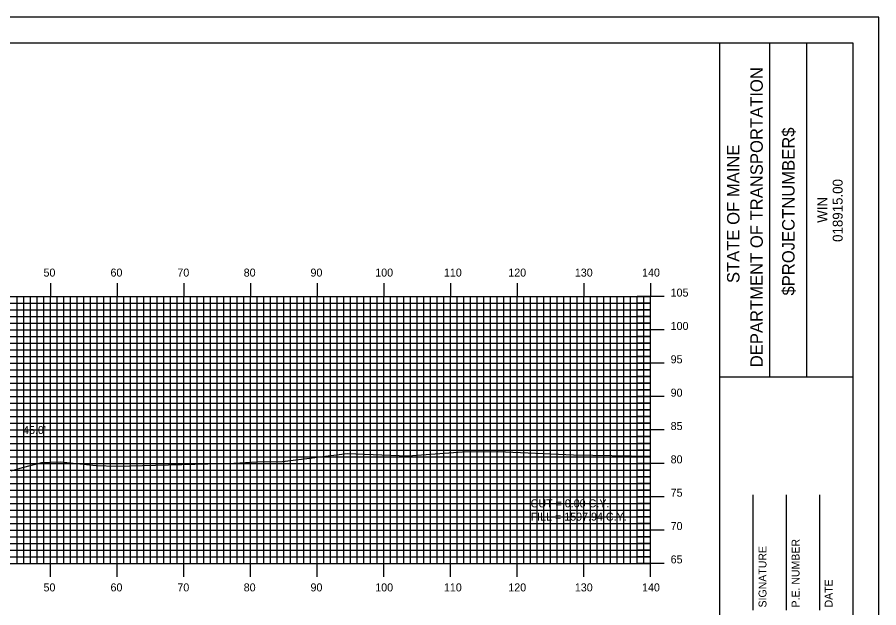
# Model space of a CAD drawing. Extents: x 857110 to 857453, y 364765 to 364985.
# Drawn here: x 857320.8 to 857450, y 364896.6 to 364985.2 of the extents above; entities that cross this region are included whole.
import ezdxf

# ---------------------------------------------------------------- set-up
doc = ezdxf.new("R2010")
doc.units = 0
for name, color, linetype in [('BORDER', 7, 'Continuous'), ('D_Text_Standard', 7, 'Continuous'), ('H_V ANNOTATION', 7, 'Continuous'), ('MAJOR', 7, 'Continuous'), ('MINOR', 7, 'Continuous'), ('PLOT BOUNDARY', 7, 'Continuous'), ('S_Roadway_Centerline', 7, 'Continuous')]:
    doc.layers.add(name, color=color, linetype=linetype)

msp = doc.modelspace()

# ---------------------------------------------------------------- linework, layer by layer
at = {"layer": 'BORDER'}
for p, q in [((857426.19, 364771.3), (857426.19, 364981.3)), ((857433.65, 364931.3), (857433.65, 364981.3)), ((857439.24, 364931.3), (857439.24, 364981.3)), ((857426.2, 364931.29), (857446.19, 364931.29)), ((857431.19, 364896.31), (857431.19, 364913.6)), ((857436.19, 364896.31), (857436.19, 364913.6)), ((857441.19, 364896.31), (857441.19, 364913.6))]:
    msp.add_line(p, q, dxfattribs=at)
msp.add_lwpolyline([(857126.19, 364771.3), (857446.19, 364771.3), (857446.19, 364981.3), (857126.19, 364981.3)], close=True, dxfattribs=at)
at = {"layer": 'MAJOR'}
for p, q in [((857325.79, 364945.31), (857325.79, 364943.3)), ((857335.79, 364945.31), (857335.79, 364943.3)), ((857345.79, 364945.31), (857345.79, 364943.3)), ((857355.79, 364945.31), (857355.79, 364943.3)), ((857365.79, 364945.31), (857365.79, 364943.3)), ((857375.79, 364945.31), (857375.79, 364943.3)), ((857385.79, 364945.31), (857385.79, 364943.3)), ((857395.79, 364945.31), (857395.79, 364943.3)), ((857405.79, 364945.31), (857405.79, 364943.3)), ((857415.79, 364945.31), (857415.79, 364943.3)), ((857135.79, 364943.3), (857415.79, 364943.3)), ((857135.79, 364943.3), (857415.79, 364943.3)), ((857325.79, 364903.3), (857325.79, 364943.3)), ((857335.79, 364903.3), (857335.79, 364943.3)), ((857345.79, 364903.3), (857345.79, 364943.3)), ((857355.79, 364903.3), (857355.79, 364943.3)), ((857365.79, 364903.3), (857365.79, 364943.3)), ((857375.79, 364903.3), (857375.79, 364943.3)), ((857385.79, 364903.3), (857385.79, 364943.3)), ((857395.79, 364903.3), (857395.79, 364943.3)), ((857405.79, 364903.3), (857405.79, 364943.3)), ((857417.8, 364943.3), (857413.79, 364943.3)), ((857415.79, 364903.3), (857415.79, 364943.3)), ((857415.79, 364903.3), (857415.79, 364943.3)), ((857135.79, 364938.3), (857415.79, 364938.3)), ((857417.8, 364938.3), (857413.79, 364938.3)), ((857135.79, 364933.3), (857415.79, 364933.3)), ((857417.8, 364933.3), (857413.79, 364933.3)), ((857135.79, 364928.3), (857415.79, 364928.3)), ((857417.8, 364928.3), (857413.79, 364928.3)), ((857135.79, 364923.3), (857415.79, 364923.3)), ((857417.8, 364923.3), (857413.79, 364923.3)), ((857135.79, 364918.3), (857415.79, 364918.3)), ((857417.8, 364918.3), (857413.79, 364918.3)), ((857135.79, 364913.3), (857415.79, 364913.3)), ((857417.8, 364913.3), (857413.79, 364913.3)), ((857135.79, 364908.3), (857415.79, 364908.3)), ((857417.8, 364908.3), (857413.79, 364908.3)), ((857135.79, 364903.3), (857415.79, 364903.3)), ((857135.79, 364903.3), (857415.79, 364903.3)), ((857325.79, 364901.3), (857325.79, 364903.3)), ((857335.79, 364901.3), (857335.79, 364903.3)), ((857345.79, 364901.3), (857345.79, 364903.3)), ((857355.79, 364901.3), (857355.79, 364903.3)), ((857365.79, 364901.3), (857365.79, 364903.3)), ((857375.79, 364901.3), (857375.79, 364903.3)), ((857385.79, 364901.3), (857385.79, 364903.3)), ((857395.79, 364901.3), (857395.79, 364903.3)), ((857405.79, 364901.3), (857405.79, 364903.3)), ((857417.8, 364903.3), (857413.79, 364903.3)), ((857415.79, 364901.3), (857415.79, 364903.3))]:
    msp.add_line(p, q, dxfattribs=at)
at = {"layer": 'MINOR'}
for p, q in [((857320.79, 364903.3), (857320.79, 364943.3)), ((857321.79, 364903.3), (857321.79, 364943.3)), ((857322.79, 364903.3), (857322.79, 364943.3)), ((857323.79, 364903.3), (857323.79, 364943.3)), ((857324.79, 364903.3), (857324.79, 364943.3)), ((857326.79, 364903.3), (857326.79, 364943.3)), ((857327.79, 364903.3), (857327.79, 364943.3)), ((857328.79, 364903.3), (857328.79, 364943.3)), ((857329.79, 364903.3), (857329.79, 364943.3)), ((857330.79, 364903.3), (857330.79, 364943.3)), ((857331.79, 364903.3), (857331.79, 364943.3)), ((857332.79, 364903.3), (857332.79, 364943.3)), ((857333.79, 364903.3), (857333.79, 364943.3)), ((857334.79, 364903.3), (857334.79, 364943.3)), ((857336.79, 364903.3), (857336.79, 364943.3)), ((857337.79, 364903.3), (857337.79, 364943.3)), ((857338.79, 364903.3), (857338.79, 364943.3)), ((857339.79, 364903.3), (857339.79, 364943.3)), ((857340.79, 364903.3), (857340.79, 364943.3)), ((857341.79, 364903.3), (857341.79, 364943.3)), ((857342.79, 364903.3), (857342.79, 364943.3)), ((857343.79, 364903.3), (857343.79, 364943.3)), ((857344.79, 364903.3), (857344.79, 364943.3)), ((857346.79, 364903.3), (857346.79, 364943.3)), ((857347.79, 364903.3), (857347.79, 364943.3)), ((857348.79, 364903.3), (857348.79, 364943.3)), ((857349.79, 364903.3), (857349.79, 364943.3)), ((857350.79, 364903.3), (857350.79, 364943.3)), ((857351.79, 364903.3), (857351.79, 364943.3)), ((857352.79, 364903.3), (857352.79, 364943.3)), ((857353.79, 364903.3), (857353.79, 364943.3)), ((857354.79, 364903.3), (857354.79, 364943.3)), ((857356.79, 364903.3), (857356.79, 364943.3)), ((857357.79, 364903.3), (857357.79, 364943.3)), ((857358.79, 364903.3), (857358.79, 364943.3)), ((857359.79, 364903.3), (857359.79, 364943.3)), ((857360.79, 364903.3), (857360.79, 364943.3)), ((857361.79, 364903.3), (857361.79, 364943.3)), ((857362.79, 364903.3), (857362.79, 364943.3)), ((857363.79, 364903.3), (857363.79, 364943.3)), ((857364.79, 364903.3), (857364.79, 364943.3)), ((857366.79, 364903.3), (857366.79, 364943.3)), ((857367.79, 364903.3), (857367.79, 364943.3)), ((857368.79, 364903.3), (857368.79, 364943.3)), ((857369.79, 364903.3), (857369.79, 364943.3)), ((857370.79, 364903.3), (857370.79, 364943.3)), ((857371.79, 364903.3), (857371.79, 364943.3)), ((857372.79, 364903.3), (857372.79, 364943.3)), ((857373.79, 364903.3), (857373.79, 364943.3)), ((857374.79, 364903.3), (857374.79, 364943.3)), ((857376.79, 364903.3), (857376.79, 364943.3)), ((857377.79, 364903.3), (857377.79, 364943.3)), ((857378.79, 364903.3), (857378.79, 364943.3)), ((857379.79, 364903.3), (857379.79, 364943.3)), ((857380.79, 364903.3), (857380.79, 364943.3)), ((857381.79, 364903.3), (857381.79, 364943.3)), ((857382.79, 364903.3), (857382.79, 364943.3)), ((857383.79, 364903.3), (857383.79, 364943.3)), ((857384.79, 364903.3), (857384.79, 364943.3)), ((857386.79, 364903.3), (857386.79, 364943.3)), ((857387.79, 364903.3), (857387.79, 364943.3)), ((857388.79, 364903.3), (857388.79, 364943.3)), ((857389.79, 364903.3), (857389.79, 364943.3)), ((857390.79, 364903.3), (857390.79, 364943.3)), ((857391.79, 364903.3), (857391.79, 364943.3)), ((857392.79, 364903.3), (857392.79, 364943.3)), ((857393.79, 364903.3), (857393.79, 364943.3)), ((857394.79, 364903.3), (857394.79, 364943.3)), ((857396.79, 364903.3), (857396.79, 364943.3)), ((857397.79, 364903.3), (857397.79, 364943.3)), ((857398.79, 364903.3), (857398.79, 364943.3)), ((857399.79, 364903.3), (857399.79, 364943.3)), ((857400.79, 364903.3), (857400.79, 364943.3)), ((857401.79, 364903.3), (857401.79, 364943.3)), ((857402.79, 364903.3), (857402.79, 364943.3)), ((857403.79, 364903.3), (857403.79, 364943.3)), ((857404.79, 364903.3), (857404.79, 364943.3)), ((857406.79, 364903.3), (857406.79, 364943.3)), ((857407.79, 364903.3), (857407.79, 364943.3)), ((857408.79, 364903.3), (857408.79, 364943.3)), ((857409.79, 364903.3), (857409.79, 364943.3)), ((857410.79, 364903.3), (857410.79, 364943.3)), ((857411.79, 364903.3), (857411.79, 364943.3)), ((857412.79, 364903.3), (857412.79, 364943.3)), ((857413.79, 364903.3), (857413.79, 364943.3)), ((857414.79, 364903.3), (857414.79, 364943.3)), ((857135.79, 364942.3), (857415.79, 364942.3)), ((857415.79, 364942.3), (857413.79, 364942.3)), ((857135.79, 364941.3), (857415.79, 364941.3)), ((857135.79, 364940.3), (857415.79, 364940.3)), ((857415.79, 364941.3), (857413.79, 364941.3)), ((857415.79, 364940.3), (857413.79, 364940.3)), ((857135.79, 364939.3), (857415.79, 364939.3)), ((857415.79, 364939.3), (857413.79, 364939.3)), ((857135.79, 364937.3), (857415.79, 364937.3)), ((857135.79, 364936.3), (857415.79, 364936.3)), ((857415.79, 364937.3), (857413.79, 364937.3)), ((857415.79, 364936.3), (857413.79, 364936.3)), ((857135.79, 364935.3), (857415.79, 364935.3)), ((857415.79, 364935.3), (857413.79, 364935.3)), ((857135.79, 364934.3), (857415.79, 364934.3)), ((857415.79, 364934.3), (857413.79, 364934.3)), ((857135.79, 364932.3), (857415.79, 364932.3)), ((857135.79, 364931.3), (857415.79, 364931.3)), ((857415.79, 364932.3), (857413.79, 364932.3)), ((857415.79, 364931.3), (857413.79, 364931.3)), ((857135.79, 364930.3), (857415.79, 364930.3)), ((857415.79, 364930.3), (857413.79, 364930.3)), ((857135.79, 364929.3), (857415.79, 364929.3)), ((857415.79, 364929.3), (857413.79, 364929.3)), ((857135.79, 364927.3), (857415.79, 364927.3)), ((857415.79, 364927.3), (857413.79, 364927.3)), ((857135.79, 364926.3), (857415.79, 364926.3)), ((857415.79, 364926.3), (857413.79, 364926.3)), ((857135.79, 364925.3), (857415.79, 364925.3)), ((857415.79, 364925.3), (857413.79, 364925.3)), ((857135.79, 364924.3), (857415.79, 364924.3)), ((857415.79, 364924.3), (857413.79, 364924.3)), ((857135.79, 364922.3), (857415.79, 364922.3)), ((857415.79, 364922.3), (857413.79, 364922.3)), ((857135.79, 364921.3), (857415.79, 364921.3)), ((857415.79, 364921.3), (857413.79, 364921.3)), ((857135.79, 364920.3), (857415.79, 364920.3)), ((857415.79, 364920.3), (857413.79, 364920.3)), ((857135.79, 364919.3), (857415.79, 364919.3)), ((857415.79, 364919.3), (857413.79, 364919.3)), ((857135.79, 364917.3), (857415.79, 364917.3)), ((857415.79, 364917.3), (857413.79, 364917.3)), ((857135.79, 364916.3), (857415.79, 364916.3)), ((857415.79, 364916.3), (857413.79, 364916.3)), ((857135.79, 364915.3), (857415.79, 364915.3)), ((857135.79, 364914.3), (857415.79, 364914.3)), ((857415.79, 364915.3), (857413.79, 364915.3)), ((857415.79, 364914.3), (857413.79, 364914.3)), ((857135.79, 364912.3), (857415.79, 364912.3)), ((857415.79, 364912.3), (857413.79, 364912.3)), ((857135.79, 364911.3), (857415.79, 364911.3)), ((857415.79, 364911.3), (857413.79, 364911.3)), ((857135.79, 364910.3), (857415.79, 364910.3)), ((857135.79, 364909.3), (857415.79, 364909.3)), ((857415.79, 364910.3), (857413.79, 364910.3)), ((857415.79, 364909.3), (857413.79, 364909.3)), ((857135.79, 364907.3), (857415.79, 364907.3)), ((857415.79, 364907.3), (857413.79, 364907.3)), ((857135.79, 364906.3), (857415.79, 364906.3)), ((857135.79, 364905.3), (857415.79, 364905.3)), ((857415.79, 364906.3), (857413.79, 364906.3)), ((857415.79, 364905.3), (857413.79, 364905.3)), ((857135.79, 364904.3), (857415.79, 364904.3)), ((857415.79, 364904.3), (857413.79, 364904.3))]:
    msp.add_line(p, q, dxfattribs=at)
at = {"layer": 'PLOT BOUNDARY'}
msp.add_lwpolyline([(857110.01, 364765.18), (857450.01, 364765.18), (857450.01, 364985.18), (857110.01, 364985.18)], close=True, dxfattribs=at)
at = {"layer": 'S_Roadway_Centerline'}
msp.add_lwpolyline([(857319.86, 364917.2), (857321.59, 364917.66), (857324.47, 364918.42), (857327.23, 364918.52), (857332.62, 364917.97), (857335.66, 364917.86), (857353.27, 364918.34), (857356.76, 364918.51), (857360.55, 364918.57), (857370.29, 364919.77), (857379.39, 364919.41), (857387.55, 364920.03), (857392.88, 364920.08), (857404.23, 364919.57), (857415.79, 364919.38)], dxfattribs=at)

# ---------------------------------------------------------------- texts
at = {"layer": 'BORDER'}
for s, height, p in [('DEPARTMENT OF TRANSPORTATION', 1.8635, (857432.61, 364932.71)), ('$PROJECTNUMBER$', 1.8635, (857437.38, 364943.46)), ('STATE OF MAINE', 1.8635, (857429.11, 364945.33)), ('018915.00', 1.491, (857444.59, 364951.5)), ('WIN', 1.491, (857442.27, 364954.36)), ('P.E. NUMBER', 1.1811, (857438.12, 364896.69)), ('SIGNATURE', 1.181, (857433.16, 364896.69)), ('DATE', 1.181, (857443.08, 364896.69))]:
    msp.add_text(s, height=height, rotation=90, dxfattribs=at).set_placement(p)
at = {"layer": 'D_Text_Standard'}
for s, p in [("45.0'", (857321.66, 364922.7)), ('CUT = 0.00 C.Y.', (857397.79, 364911.7)), ('FILL = 1597.94 C.Y.', (857397.79, 364909.71))]:
    msp.add_text(s, height=1.2, dxfattribs=at).set_placement(p)
at = {"layer": 'H_V ANNOTATION'}
for s, p in [('50', (857324.72, 364946.3)), ('60', (857334.77, 364946.3)), ('70', (857344.8, 364946.3)), ('80', (857354.75, 364946.3)), ('90', (857364.77, 364946.3)), ('100', (857374.48, 364946.3)), ('110', (857384.78, 364946.3)), ('120', (857394.44, 364946.3)), ('130', (857404.42, 364946.3)), ('140', (857414.5, 364946.3)), ('105', (857418.79, 364943.3)), ('100', (857418.79, 364938.3)), ('95', (857418.79, 364933.3)), ('90', (857418.79, 364928.3)), ('85', (857418.79, 364923.3)), ('80', (857418.79, 364918.3)), ('75', (857418.79, 364913.3)), ('70', (857418.79, 364908.3)), ('65', (857418.79, 364903.3)), ('50', (857324.72, 364899.1)), ('60', (857334.77, 364899.1)), ('70', (857344.8, 364899.1)), ('80', (857354.75, 364899.1)), ('90', (857364.77, 364899.1)), ('100', (857374.48, 364899.1)), ('110', (857384.78, 364899.1)), ('120', (857394.44, 364899.1)), ('130', (857404.42, 364899.1)), ('140', (857414.5, 364899.1))]:
    msp.add_text(s, height=1.2, dxfattribs=at).set_placement(p)

doc.saveas('drawing.dxf')
